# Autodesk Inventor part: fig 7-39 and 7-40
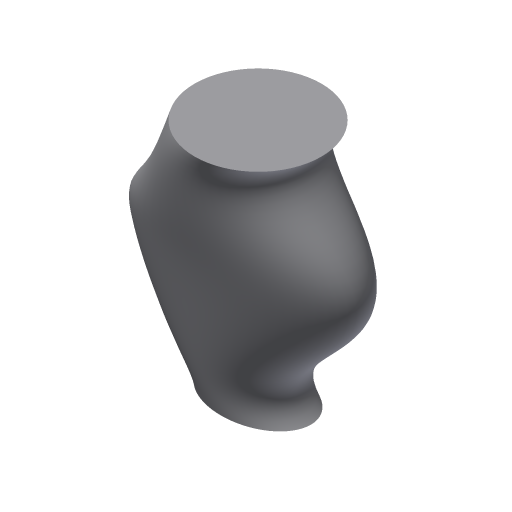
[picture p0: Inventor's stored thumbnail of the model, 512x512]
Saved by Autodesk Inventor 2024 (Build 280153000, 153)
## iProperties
Shininess: 64.0
Length Units: 11269
Angle Units: 11279
Time Units: 11290
Mass Units: 11283
Length Display Precision: 3
Angle Display Precision: 2
Compacted: True
Part Number: fig 7-39 and 7-40
Document SubType Name: Modeling
Created: 2002-12
Designer: deepak
Density: 1 g/cm^3
Material: Generic
Appearance: Default
Density: 0.0
Volumn: 0.0
Area: 0.0
PropertySet Name: Model Information
Control State: 0
Master: False
Checked Out: False
Author: deepak
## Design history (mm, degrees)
sketch "Sketch1"
  geometry: 2 further points; 1 other entity
  constraints: 1 coincident, 3 other
workplane "Work Plane1"
workplane "Work Plane2"
sketch "Sketch3"
  geometry: C1 r 60 at (0, 0); 1 further point
  constraints: 1 centre point, 1 coincident, 1 other
sketch "Sketch4"
  geometry: 8 further points
  constraints: 8 other
sketch "Sketch5"
  geometry: 6 further points
  constraints: 6 other
sketch "Sketch6"
  geometry: 6 further points
  constraints: 6 other
  dimensions: "d20" = 35 distance of point (0, 0) point (-35, 0); "d21" = 0 vertical distance of point (0, 0) point (-35, 0); "d22" = 225 vertical distance of point (0, 0) point (-60, 225); "d23" = 60 horizontal distance of point (0, 0) point (-60, 225); "d24" = 100 horizontal distance of point (0, 0) point (-100, 125); "d25" = 125 vertical distance of point (0, 0) point (-100, 125)
loft "Loft3" dims "d42" = 0, "d43" = 90 deg, "d44" = 0, "d45" = 90 deg, "d46" = 0, "d47" = 90 deg, "d48" = 0, "d49" = 90 deg
body "Solid1"
node "Sketch7"
sketch "Sketch8"
  geometry: 1 further point
other parameters: "d5" = 125
